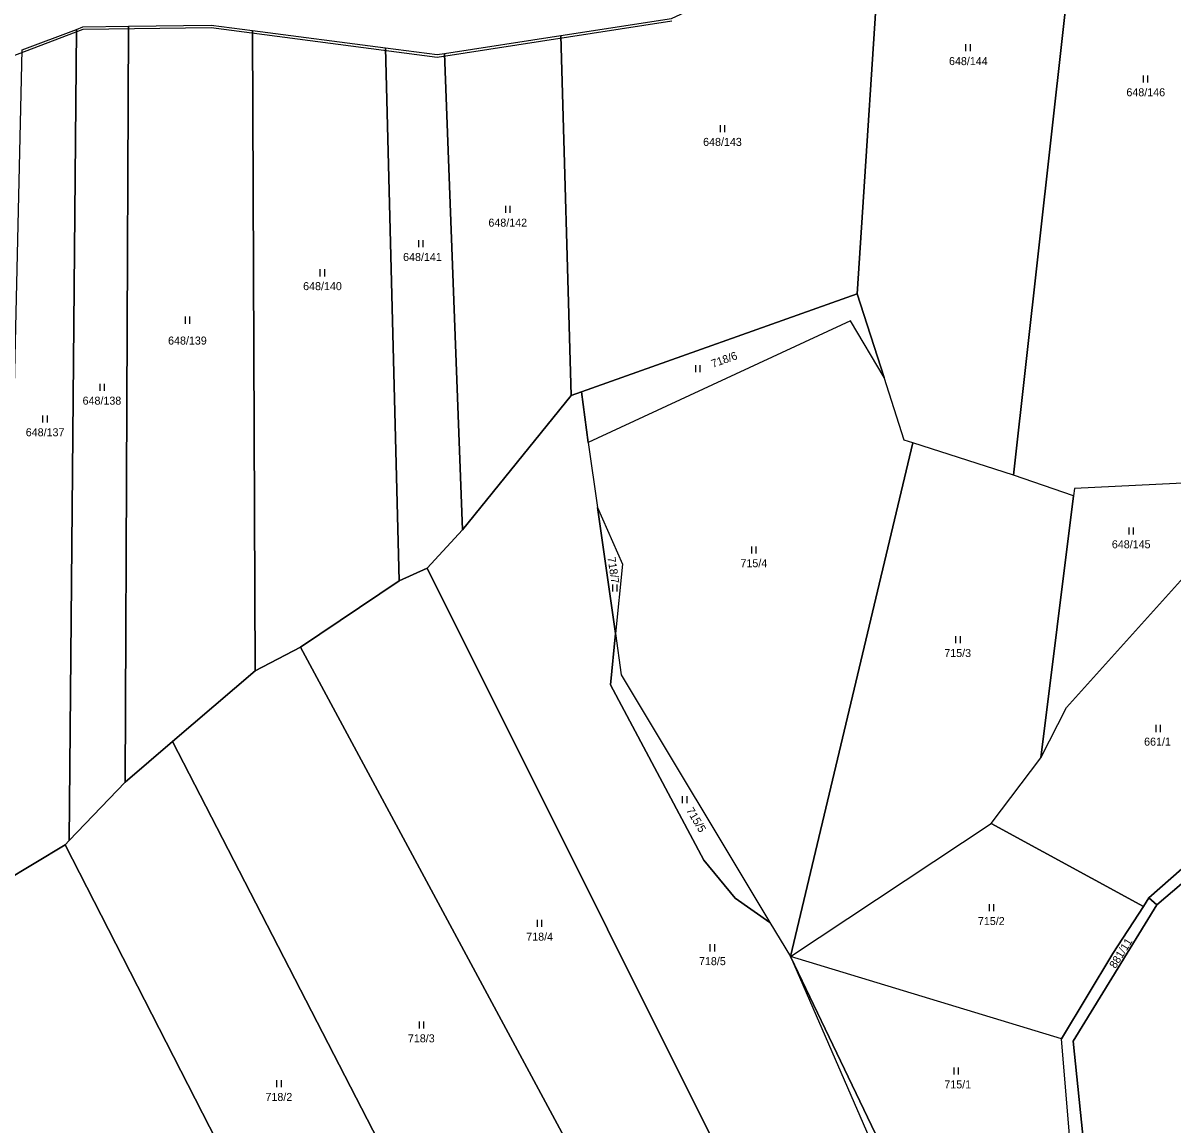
# Model space of a CAD drawing. Extents: x -654083 to -650132, y -1099819 to -1096699.
# Drawn here: x -652530.5 to -652286.2, y -1098817.7 to -1098583.8 of the extents above; entities that cross this region are included whole.
import ezdxf

# ---------------------------------------------------------------- set-up
doc = ezdxf.new("R2010")
doc.units = 0
for name, color, linetype in [('Obvody jako plochy', 7, 'Continuous'), ('Ostatní hranice', 7, 'Continuous'), ('Parcelní čísla', 7, 'Continuous'), ('Značky kultur', 7, 'Continuous')]:
    doc.layers.add(name, color=color, linetype=linetype)

msp = doc.modelspace()

# ---------------------------------------------------------------- linework, layer by layer
at = {"layer": 'Obvody jako plochy'}
for points in [[(-652264.57, -1098533.1), (-652281.26, -1098681.4), (-652307.2, -1098682.68), (-652307.39, -1098684.23), (-652320.12, -1098679.86), (-652304.18, -1098536.87), (-652279, -1098531.51), (-652266.09, -1098528.97)], [(-652304.18, -1098536.87), (-652320.12, -1098679.86), (-652341.51, -1098673.02), (-652343.36, -1098672.43), (-652347.62, -1098659.13), (-652353.3, -1098641.38), (-652348.01, -1098560.01), (-652315.53, -1098539.28)], [(-652348.01, -1098560.01), (-652353.3, -1098641.38), (-652411.88, -1098662.18), (-652414.07, -1098662.96), (-652416.29, -1098586.5), (-652392.78, -1098582.87), (-652359.39, -1098567.27)], [(-652521.52, -1098758.36), (-652534.7, -1098766.31), (-652530.65, -1098589.56), (-652519.14, -1098585.18), (-652520.65, -1098757.47)], [(-652508.81, -1098745.1), (-652520.65, -1098757.47), (-652519.14, -1098585.18), (-652517.75, -1098584.65), (-652508.06, -1098584.52)], [(-652498.72, -1098736.46), (-652508.81, -1098745.1), (-652508.06, -1098584.52), (-652490.53, -1098584.29), (-652481.75, -1098585.43), (-652481.21, -1098721.45)], [(-652481.75, -1098585.43), (-652453.47, -1098589.12), (-652450.6, -1098702.35), (-652471.55, -1098716.38), (-652481.21, -1098721.45)], [(-652414.07, -1098662.96), (-652437.16, -1098691.45), (-652440.94, -1098590.3), (-652416.29, -1098586.5)], [(-652453.47, -1098589.12), (-652442.53, -1098590.55), (-652440.94, -1098590.3), (-652437.16, -1098691.45), (-652444.65, -1098699.64), (-652450.6, -1098702.35)], [(-652354.73, -1098647.11), (-652410.45, -1098672.92), (-652411.88, -1098662.18), (-652353.3, -1098641.38), (-652347.62, -1098659.13)], [(-652341.51, -1098673.02), (-652343.36, -1098672.43), (-652347.62, -1098659.13), (-652354.73, -1098647.11), (-652410.45, -1098672.92), (-652408.49, -1098686.72), (-652403.17, -1098698.76), (-652404.68, -1098713.47), (-652403.43, -1098722.28), (-652371.85, -1098774.86), (-652367.5, -1098782.1)], [(-652410.45, -1098672.92), (-652408.49, -1098686.72), (-652404.68, -1098713.47), (-652405.7, -1098724.42), (-652385.88, -1098761.64), (-652379.26, -1098769.7), (-652371.85, -1098774.86), (-652367.5, -1098782.1), (-652343.25, -1098837.74), (-652341.27, -1098836.75), (-652340.22, -1098838.94), (-652368.06, -1098852.99), (-652444.65, -1098699.64), (-652437.16, -1098691.45), (-652414.07, -1098662.96), (-652411.88, -1098662.18)], [(-652320.12, -1098679.86), (-652341.51, -1098673.02), (-652367.5, -1098782.1), (-652324.84, -1098753.87), (-652314.29, -1098739.9), (-652307.39, -1098684.23)], [(-652314.29, -1098739.9), (-652308.87, -1098729.25), (-652283.39, -1098700.92), (-652281.26, -1098681.4), (-652307.2, -1098682.68), (-652307.39, -1098684.23)], [(-652408.49, -1098686.72), (-652403.17, -1098698.76), (-652404.68, -1098713.47)], [(-652368.06, -1098852.99), (-652391.78, -1098864.61), (-652471.55, -1098716.38), (-652450.6, -1098702.35), (-652444.65, -1098699.64)], [(-652283.39, -1098700.92), (-652253.97, -1098736.82), (-652291.36, -1098769.66), (-652292.49, -1098771.49), (-652324.84, -1098753.87), (-652314.29, -1098739.9), (-652308.87, -1098729.25)], [(-652403.43, -1098722.28), (-652371.85, -1098774.86), (-652379.26, -1098769.7), (-652385.88, -1098761.64), (-652405.7, -1098724.42), (-652404.68, -1098713.47)], [(-652471.55, -1098716.38), (-652391.78, -1098864.61), (-652424.31, -1098880.81), (-652498.72, -1098736.46), (-652481.21, -1098721.45)], [(-652243.3, -1098766.39), (-652285.69, -1098840.06), (-652293.9, -1098834.53), (-652304.92, -1098824.89), (-652307.45, -1098800.06), (-652289.68, -1098771.17), (-652252.11, -1098739.11), (-652245.36, -1098731.34), (-652245.38, -1098733.09), (-652237.09, -1098732.54), (-652234.48, -1098731.49)], [(-652437.48, -1098887.85), (-652452.51, -1098893.28), (-652521.52, -1098758.36), (-652520.65, -1098757.47), (-652508.81, -1098745.1), (-652498.72, -1098736.46), (-652424.31, -1098880.81)], [(-652253.97, -1098736.82), (-652252.11, -1098739.11), (-652289.68, -1098771.17), (-652291.36, -1098769.66)], [(-652292.49, -1098771.49), (-652299.03, -1098781.45), (-652309.95, -1098799.61), (-652367.5, -1098782.1), (-652324.84, -1098753.87)], [(-652452.51, -1098893.28), (-652489.4, -1098908.18), (-652496.8, -1098910.33), (-652509.63, -1098896.65), (-652518.74, -1098863.59), (-652527.47, -1098851.14), (-652526.09, -1098839.17), (-652532.1, -1098827.19), (-652546.11, -1098816.23), (-652548.42, -1098807.57), (-652553.68, -1098802.81), (-652545.83, -1098787.84), (-652534.7, -1098766.31), (-652521.52, -1098758.36)], [(-652291.36, -1098769.66), (-652289.68, -1098771.17), (-652307.45, -1098800.06), (-652304.92, -1098824.89), (-652307.91, -1098823.43), (-652309.95, -1098799.61), (-652299.03, -1098781.45), (-652292.49, -1098771.49)], [(-652307.91, -1098823.43), (-652309.95, -1098799.61), (-652367.5, -1098782.1), (-652341.27, -1098836.75), (-652332.62, -1098832.03)], [(-652341.27, -1098836.75), (-652367.5, -1098782.1), (-652343.25, -1098837.74)]]:
    msp.add_lwpolyline(points, close=True, dxfattribs=at)
msp.add_lwpolyline([(-652530.65, -1098589.56), (-652519.14, -1098585.18), (-652517.75, -1098584.65), (-652508.06, -1098584.52), (-652490.53, -1098584.29), (-652481.75, -1098585.43), (-652453.47, -1098589.12), (-652442.53, -1098590.55), (-652440.94, -1098590.3), (-652416.29, -1098586.5), (-652392.78, -1098582.87), (-652359.39, -1098567.27), (-652348.01, -1098560.01), (-652315.53, -1098539.28), (-652304.18, -1098536.87), (-652279, -1098531.51)], dxfattribs=at)
at = {"layer": 'Ostatní hranice'}
for p, q in [((-652442.5, -1098591.05), (-652392.66, -1098583.36)), ((-652534.6, -1098591.58), (-652517.71, -1098585.15)), ((-652517.71, -1098585.15), (-652490.54, -1098584.79)), ((-652490.54, -1098584.79), (-652442.5, -1098591.05))]:
    msp.add_line(p, q, dxfattribs=at)
at = {"layer": 'Značky kultur'}
for p, q in [((-652330.28, -1098588.33), (-652330.28, -1098589.83)), ((-652329.26, -1098589.83), (-652329.26, -1098588.33)), ((-652292.6, -1098594.96), (-652292.6, -1098596.46)), ((-652291.58, -1098596.46), (-652291.58, -1098594.96)), ((-652382.42, -1098605.5), (-652382.42, -1098607)), ((-652381.4, -1098607), (-652381.4, -1098605.5)), ((-652428.03, -1098622.65), (-652428.03, -1098624.15)), ((-652427.01, -1098624.15), (-652427.01, -1098622.65)), ((-652446.52, -1098629.95), (-652446.52, -1098631.45)), ((-652445.49, -1098631.45), (-652445.49, -1098629.95)), ((-652467.43, -1098636.14), (-652467.43, -1098637.64)), ((-652466.41, -1098637.64), (-652466.41, -1098636.14)), ((-652496.05, -1098646.2), (-652496.05, -1098647.7)), ((-652495.03, -1098647.7), (-652495.03, -1098646.2)), ((-652387.66, -1098656.47), (-652387.66, -1098657.97)), ((-652386.64, -1098657.97), (-652386.64, -1098656.47)), ((-652514.18, -1098660.46), (-652514.18, -1098661.96)), ((-652513.16, -1098661.96), (-652513.16, -1098660.46)), ((-652526.32, -1098667.18), (-652526.32, -1098668.68)), ((-652525.3, -1098668.68), (-652525.3, -1098667.18)), ((-652295.65, -1098690.97), (-652295.65, -1098692.47)), ((-652294.62, -1098692.47), (-652294.62, -1098690.97)), ((-652375.8, -1098695), (-652375.8, -1098696.5)), ((-652374.78, -1098696.5), (-652374.78, -1098695)), ((-652405.32, -1098703.11), (-652405.32, -1098704.61)), ((-652404.3, -1098704.61), (-652404.3, -1098703.11)), ((-652332.43, -1098714.06), (-652332.43, -1098715.56)), ((-652331.41, -1098715.56), (-652331.41, -1098714.06)), ((-652289.92, -1098732.93), (-652289.92, -1098734.43)), ((-652288.9, -1098734.43), (-652288.9, -1098732.93)), ((-652390.46, -1098748.02), (-652390.46, -1098749.52)), ((-652389.44, -1098749.52), (-652389.44, -1098748.02)), ((-652325.31, -1098771), (-652325.31, -1098772.5)), ((-652324.29, -1098772.5), (-652324.29, -1098771)), ((-652421.31, -1098774.31), (-652421.31, -1098775.81)), ((-652420.29, -1098775.81), (-652420.29, -1098774.31)), ((-652384.59, -1098779.52), (-652384.59, -1098781.02)), ((-652383.57, -1098781.02), (-652383.57, -1098779.52)), ((-652446.37, -1098795.91), (-652446.37, -1098797.41)), ((-652445.34, -1098797.41), (-652445.34, -1098795.91)), ((-652332.81, -1098805.7), (-652332.81, -1098807.2)), ((-652331.79, -1098807.2), (-652331.79, -1098805.7)), ((-652476.63, -1098808.35), (-652476.63, -1098809.85)), ((-652475.6, -1098809.85), (-652475.6, -1098808.35))]:
    msp.add_line(p, q, dxfattribs=at)

# ---------------------------------------------------------------- texts
at = {"layer": 'Parcelní čísla'}
for s, p in [('648/144', (-652333.82, -1098592.77)), ('648/146', (-652296.14, -1098599.39)), ('648/143', (-652386.04, -1098609.93)), ('648/142', (-652431.64, -1098627.08)), ('648/141', (-652449.76, -1098634.38)), ('648/140', (-652470.99, -1098640.57)), ('648/139', (-652499.67, -1098652.13)), ('648/138', (-652517.83, -1098664.89)), ('648/137', (-652529.9, -1098671.61)), ('648/145', (-652299.23, -1098695.4)), ('715/4', (-652378.11, -1098699.43)), ('715/3', (-652334.82, -1098718.5)), ('661/1', (-652292.38, -1098737.32)), ('715/2', (-652327.68, -1098775.43)), ('718/4', (-652423.6, -1098778.75)), ('718/5', (-652386.92, -1098783.95)), ('718/3', (-652448.74, -1098800.34)), ('715/1', (-652334.81, -1098810.13)), ('718/2', (-652478.99, -1098812.79))]:
    msp.add_text(s, height=1.7, dxfattribs=at).set_placement(p)
for s, rotation, p in [('718/6', 19.719, (-652383.96, -1098657.08)), ('718/7', 278.415, (-652406.35, -1098697.37)), ('715/5', 300.654, (-652389.67, -1098751.05)), ('881/11', 57.969, (-652298.47, -1098784.79))]:
    msp.add_text(s, height=1.7, rotation=rotation, dxfattribs=at).set_placement(p)

doc.saveas('drawing.dxf')
